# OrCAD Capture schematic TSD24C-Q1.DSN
size A; title: TSDxxC-Q1 Bidrectional TVS Diodes in SOD-323 Package; rev: 1.0; note: Datasheet: SLVSHX0
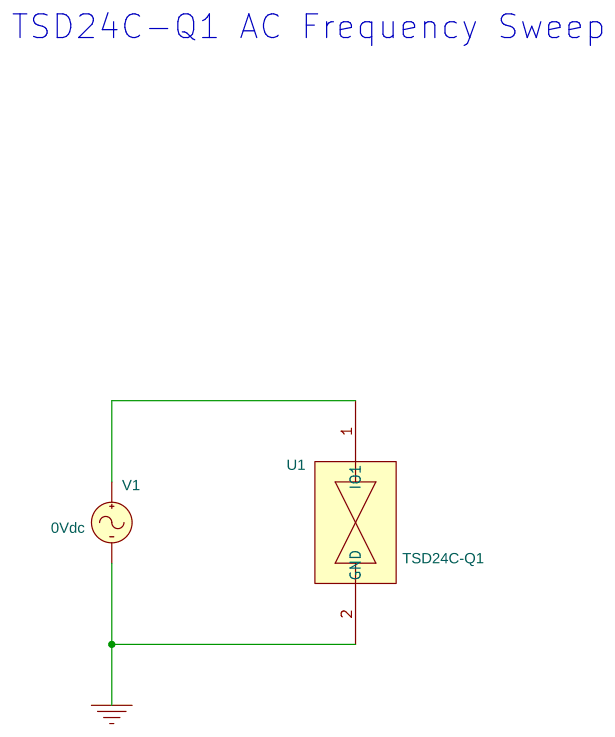
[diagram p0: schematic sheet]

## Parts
U1  TSD24C-Q1
V1  VAC

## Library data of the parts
U1 = TSD24C-Q1
V1 = VAC: DC: 0Vdc

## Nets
0: U1.2(GND) V1.2(-)
N02888: U1.1(IO1) V1.1(+)

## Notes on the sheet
- TSD24C-Q1 AC Frequency Sweep
